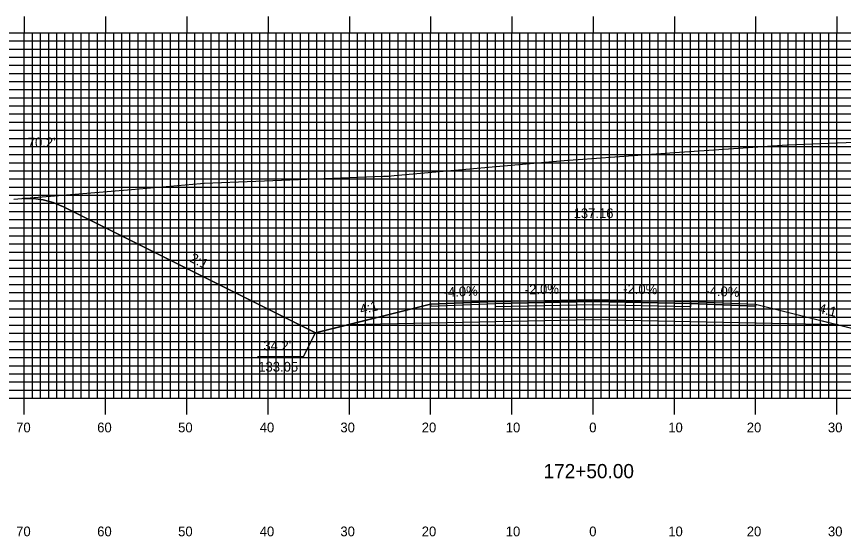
# Model space of a CAD drawing. Extents: x 1783041 to 1783384, y 442591 to 442811.
# Drawn here: x 1783135.5 to 1783237.3, y 442656.6 to 442720.7 of the extents above; entities that cross this region are included whole.
import ezdxf

# ---------------------------------------------------------------- set-up
doc = ezdxf.new("R2010")
doc.units = 0
for name, color, linetype in [('ANNOTATION', 7, 'Continuous'), ('D_Roadway_Centerline', 7, 'Continuous'), ('D_Roadway_Centerline_Text', 7, 'Continuous'), ('D_Roadway_Edge_Shoulder', 7, 'Continuous'), ('D_Roadway_Edge_TW', 7, 'Continuous'), ('D_Roadway_Pavement', 7, 'Continuous'), ('D_Roadway_SlopeLines', 7, 'Continuous'), ('D_Roadway_SubGrade', 7, 'Continuous'), ('D_Text_Standard', 7, 'Continuous'), ('H_V ANNOTATION', 7, 'Continuous'), ('MAJOR', 7, 'Continuous'), ('MINOR', 7, 'Continuous'), ('S_Roadway_Centerline', 7, 'Continuous')]:
    doc.layers.add(name, color=color, linetype=linetype)

msp = doc.modelspace()

# ---------------------------------------------------------------- linework, layer by layer
at = {"layer": 'ANNOTATION'}
msp.add_lwpolyline([(1783165.14, 442678.82), (1783170.83, 442678.82), (1783172.29, 442681.72)], dxfattribs=at)
at = {"layer": 'D_Roadway_Centerline'}
msp.add_lwpolyline([(1783136.28, 442698.26), (1783137.53, 442698.27), (1783138.78, 442698.11), (1783140.03, 442697.76), (1783141.28, 442697.22), (1783172.29, 442681.72), (1783176.29, 442682.72), (1783186.46, 442685.26), (1783194.46, 442685.58), (1783206.46, 442685.82), (1783218.46, 442685.58), (1783226.46, 442685.26), (1783236.63, 442682.72), (1783242.72, 442681.2), (1783297.77, 442708.72), (1783299.02, 442709.26), (1783300.27, 442709.64), (1783301.52, 442709.85), (1783302.77, 442709.89)], dxfattribs=at)
at = {"layer": 'D_Roadway_Edge_Shoulder'}
for points in [[(1783194.46, 442685.58), (1783186.46, 442685.26), (1783186.46, 442685.01), (1783194.46, 442685.33)], [(1783218.46, 442685.58), (1783226.46, 442685.26), (1783226.46, 442685.01), (1783218.46, 442685.33)]]:
    msp.add_lwpolyline(points, close=True, dxfattribs=at)
at = {"layer": 'D_Roadway_Edge_TW'}
msp.add_lwpolyline([(1783194.46, 442685.33), (1783194.46, 442685.58), (1783206.46, 442685.82), (1783218.46, 442685.58), (1783218.46, 442685.33), (1783206.46, 442685.57)], close=True, dxfattribs=at)
at = {"layer": 'D_Roadway_Pavement'}
msp.add_lwpolyline([(1783194.46, 442684.91), (1783194.46, 442685.33), (1783206.46, 442685.57), (1783218.46, 442685.33), (1783218.46, 442684.91), (1783206.46, 442685.15)], close=True, dxfattribs=at)
at = {"layer": 'D_Roadway_SlopeLines'}
for points in [[(1783172.29, 442681.72), (1783141.28, 442697.22), (1783140.03, 442697.76), (1783138.78, 442698.11), (1783137.53, 442698.27), (1783136.28, 442698.26)], [(1783186.46, 442685.26), (1783172.29, 442681.72)], [(1783226.46, 442685.26), (1783242.72, 442681.2)]]:
    msp.add_lwpolyline(points, dxfattribs=at)
at = {"layer": 'D_Roadway_SubGrade'}
msp.add_lwpolyline([(1783194.46, 442683.08), (1783176.29, 442682.72), (1783186.46, 442685.26), (1783186.46, 442685.01), (1783194.46, 442685.33), (1783206.46, 442685.57), (1783218.46, 442685.33), (1783226.46, 442685.01), (1783226.46, 442685.26), (1783236.63, 442682.72), (1783218.46, 442683.08), (1783206.46, 442683.32)], close=True, dxfattribs=at)
at = {"layer": 'MAJOR'}
for p, q in [((1783136.46, 442720.67), (1783136.46, 442718.67)), ((1783146.46, 442720.67), (1783146.46, 442718.67)), ((1783156.46, 442720.67), (1783156.46, 442718.67)), ((1783166.46, 442720.67), (1783166.46, 442718.67)), ((1783176.46, 442720.67), (1783176.46, 442718.67)), ((1783186.46, 442720.67), (1783186.46, 442718.67)), ((1783196.46, 442720.67), (1783196.46, 442718.67)), ((1783206.46, 442720.67), (1783206.46, 442718.67)), ((1783216.46, 442720.67), (1783216.46, 442718.67)), ((1783226.46, 442720.67), (1783226.46, 442718.67)), ((1783236.46, 442720.67), (1783236.46, 442718.67)), ((1783066.46, 442718.67), (1783346.46, 442718.67)), ((1783066.46, 442718.67), (1783346.46, 442718.67)), ((1783136.46, 442673.67), (1783136.46, 442718.67)), ((1783146.46, 442673.67), (1783146.46, 442718.67)), ((1783156.46, 442673.67), (1783156.46, 442718.67)), ((1783166.46, 442673.67), (1783166.46, 442718.67)), ((1783176.46, 442673.67), (1783176.46, 442718.67)), ((1783186.46, 442673.67), (1783186.46, 442718.67)), ((1783196.46, 442673.67), (1783196.46, 442718.67)), ((1783206.46, 442673.67), (1783206.46, 442718.67)), ((1783216.46, 442673.67), (1783216.46, 442718.67)), ((1783226.46, 442673.67), (1783226.46, 442718.67)), ((1783236.46, 442673.67), (1783236.46, 442718.67)), ((1783066.46, 442713.67), (1783346.46, 442713.67)), ((1783066.46, 442708.67), (1783346.46, 442708.67)), ((1783066.46, 442703.67), (1783346.46, 442703.67)), ((1783066.46, 442698.67), (1783346.46, 442698.67)), ((1783066.46, 442693.67), (1783346.46, 442693.67)), ((1783066.46, 442688.67), (1783346.46, 442688.67)), ((1783066.46, 442683.67), (1783346.46, 442683.67)), ((1783066.46, 442678.67), (1783346.46, 442678.67)), ((1783066.46, 442673.67), (1783346.46, 442673.67)), ((1783066.46, 442673.67), (1783346.46, 442673.67)), ((1783136.46, 442671.66), (1783136.46, 442673.67)), ((1783146.46, 442671.66), (1783146.46, 442673.67)), ((1783156.46, 442671.66), (1783156.46, 442673.67)), ((1783166.46, 442671.66), (1783166.46, 442673.67)), ((1783176.46, 442671.66), (1783176.46, 442673.67)), ((1783186.46, 442671.66), (1783186.46, 442673.67)), ((1783196.46, 442671.66), (1783196.46, 442673.67)), ((1783206.46, 442671.66), (1783206.46, 442673.67)), ((1783216.46, 442671.66), (1783216.46, 442673.67)), ((1783226.46, 442671.66), (1783226.46, 442673.67)), ((1783236.46, 442671.66), (1783236.46, 442673.67))]:
    msp.add_line(p, q, dxfattribs=at)
at = {"layer": 'MINOR'}
for p, q in [((1783137.46, 442673.67), (1783137.46, 442718.67)), ((1783138.46, 442673.67), (1783138.46, 442718.67)), ((1783139.46, 442673.67), (1783139.46, 442718.67)), ((1783140.46, 442673.67), (1783140.46, 442718.67)), ((1783141.46, 442673.67), (1783141.46, 442718.67)), ((1783142.46, 442673.67), (1783142.46, 442718.67)), ((1783143.46, 442673.67), (1783143.46, 442718.67)), ((1783144.46, 442673.67), (1783144.46, 442718.67)), ((1783145.46, 442673.67), (1783145.46, 442718.67)), ((1783147.46, 442673.67), (1783147.46, 442718.67)), ((1783148.46, 442673.67), (1783148.46, 442718.67)), ((1783149.46, 442673.67), (1783149.46, 442718.67)), ((1783150.46, 442673.67), (1783150.46, 442718.67)), ((1783151.46, 442673.67), (1783151.46, 442718.67)), ((1783152.46, 442673.67), (1783152.46, 442718.67)), ((1783153.46, 442673.67), (1783153.46, 442718.67)), ((1783154.46, 442673.67), (1783154.46, 442718.67)), ((1783155.46, 442673.67), (1783155.46, 442718.67)), ((1783157.46, 442673.67), (1783157.46, 442718.67)), ((1783158.46, 442673.67), (1783158.46, 442718.67)), ((1783159.46, 442673.67), (1783159.46, 442718.67)), ((1783160.46, 442673.67), (1783160.46, 442718.67)), ((1783161.46, 442673.67), (1783161.46, 442718.67)), ((1783162.46, 442673.67), (1783162.46, 442718.67)), ((1783163.46, 442673.67), (1783163.46, 442718.67)), ((1783164.46, 442673.67), (1783164.46, 442718.67)), ((1783165.46, 442673.67), (1783165.46, 442718.67)), ((1783167.46, 442673.67), (1783167.46, 442718.67)), ((1783168.46, 442673.67), (1783168.46, 442718.67)), ((1783169.46, 442673.67), (1783169.46, 442718.67)), ((1783170.46, 442673.67), (1783170.46, 442718.67)), ((1783171.46, 442673.67), (1783171.46, 442718.67)), ((1783172.46, 442673.67), (1783172.46, 442718.67)), ((1783173.46, 442673.67), (1783173.46, 442718.67)), ((1783174.46, 442673.67), (1783174.46, 442718.67)), ((1783175.46, 442673.67), (1783175.46, 442718.67)), ((1783177.46, 442673.67), (1783177.46, 442718.67)), ((1783178.46, 442673.67), (1783178.46, 442718.67)), ((1783179.46, 442673.67), (1783179.46, 442718.67)), ((1783180.46, 442673.67), (1783180.46, 442718.67)), ((1783181.46, 442673.67), (1783181.46, 442718.67)), ((1783182.46, 442673.67), (1783182.46, 442718.67)), ((1783183.46, 442673.67), (1783183.46, 442718.67)), ((1783184.46, 442673.67), (1783184.46, 442718.67)), ((1783185.46, 442673.67), (1783185.46, 442718.67)), ((1783187.46, 442673.67), (1783187.46, 442718.67)), ((1783188.46, 442673.67), (1783188.46, 442718.67)), ((1783189.46, 442673.67), (1783189.46, 442718.67)), ((1783190.46, 442673.67), (1783190.46, 442718.67)), ((1783191.46, 442673.67), (1783191.46, 442718.67)), ((1783192.46, 442673.67), (1783192.46, 442718.67)), ((1783193.46, 442673.67), (1783193.46, 442718.67)), ((1783194.46, 442673.67), (1783194.46, 442718.67)), ((1783195.46, 442673.67), (1783195.46, 442718.67)), ((1783197.46, 442673.67), (1783197.46, 442718.67)), ((1783198.46, 442673.67), (1783198.46, 442718.67)), ((1783199.46, 442673.67), (1783199.46, 442718.67)), ((1783200.46, 442673.67), (1783200.46, 442718.67)), ((1783201.46, 442673.67), (1783201.46, 442718.67)), ((1783202.46, 442673.67), (1783202.46, 442718.67)), ((1783203.46, 442673.67), (1783203.46, 442718.67)), ((1783204.46, 442673.67), (1783204.46, 442718.67)), ((1783205.46, 442673.67), (1783205.46, 442718.67)), ((1783207.46, 442673.67), (1783207.46, 442718.67)), ((1783208.46, 442673.67), (1783208.46, 442718.67)), ((1783209.46, 442673.67), (1783209.46, 442718.67)), ((1783210.46, 442673.67), (1783210.46, 442718.67)), ((1783211.46, 442673.67), (1783211.46, 442718.67)), ((1783212.46, 442673.67), (1783212.46, 442718.67)), ((1783213.46, 442673.67), (1783213.46, 442718.67)), ((1783214.46, 442673.67), (1783214.46, 442718.67)), ((1783215.46, 442673.67), (1783215.46, 442718.67)), ((1783217.46, 442673.67), (1783217.46, 442718.67)), ((1783218.46, 442673.67), (1783218.46, 442718.67)), ((1783219.46, 442673.67), (1783219.46, 442718.67)), ((1783220.46, 442673.67), (1783220.46, 442718.67)), ((1783221.46, 442673.67), (1783221.46, 442718.67)), ((1783222.46, 442673.67), (1783222.46, 442718.67)), ((1783223.46, 442673.67), (1783223.46, 442718.67)), ((1783224.46, 442673.67), (1783224.46, 442718.67)), ((1783225.46, 442673.67), (1783225.46, 442718.67)), ((1783227.46, 442673.67), (1783227.46, 442718.67)), ((1783228.46, 442673.67), (1783228.46, 442718.67)), ((1783229.46, 442673.67), (1783229.46, 442718.67)), ((1783230.46, 442673.67), (1783230.46, 442718.67)), ((1783231.46, 442673.67), (1783231.46, 442718.67)), ((1783232.46, 442673.67), (1783232.46, 442718.67)), ((1783233.46, 442673.67), (1783233.46, 442718.67)), ((1783234.46, 442673.67), (1783234.46, 442718.67)), ((1783235.46, 442673.67), (1783235.46, 442718.67)), ((1783066.46, 442717.67), (1783346.46, 442717.67)), ((1783066.46, 442716.67), (1783346.46, 442716.67)), ((1783066.46, 442715.67), (1783346.46, 442715.67)), ((1783066.46, 442714.67), (1783346.46, 442714.67)), ((1783066.46, 442712.67), (1783346.46, 442712.67)), ((1783066.46, 442711.67), (1783346.46, 442711.67)), ((1783066.46, 442710.67), (1783346.46, 442710.67)), ((1783066.46, 442709.67), (1783346.46, 442709.67)), ((1783066.46, 442707.67), (1783346.46, 442707.67)), ((1783066.46, 442706.67), (1783346.46, 442706.67)), ((1783066.46, 442705.67), (1783346.46, 442705.67)), ((1783066.46, 442704.67), (1783346.46, 442704.67)), ((1783066.46, 442702.67), (1783346.46, 442702.67)), ((1783066.46, 442701.67), (1783346.46, 442701.67)), ((1783066.46, 442700.67), (1783346.46, 442700.67)), ((1783066.46, 442699.67), (1783346.46, 442699.67)), ((1783066.46, 442697.67), (1783346.46, 442697.67)), ((1783066.46, 442696.67), (1783346.46, 442696.67)), ((1783066.46, 442695.67), (1783346.46, 442695.67)), ((1783066.46, 442694.67), (1783346.46, 442694.67)), ((1783066.46, 442692.67), (1783346.46, 442692.67)), ((1783066.46, 442691.67), (1783346.46, 442691.67)), ((1783066.46, 442690.67), (1783346.46, 442690.67)), ((1783066.46, 442689.67), (1783346.46, 442689.67)), ((1783066.46, 442687.67), (1783346.46, 442687.67)), ((1783066.46, 442686.67), (1783346.46, 442686.67)), ((1783066.46, 442685.67), (1783346.46, 442685.67)), ((1783066.46, 442684.67), (1783346.46, 442684.67)), ((1783066.46, 442682.67), (1783346.46, 442682.67)), ((1783066.46, 442681.67), (1783346.46, 442681.67)), ((1783066.46, 442680.67), (1783346.46, 442680.67)), ((1783066.46, 442679.67), (1783346.46, 442679.67)), ((1783066.46, 442677.67), (1783346.46, 442677.67)), ((1783066.46, 442676.67), (1783346.46, 442676.67)), ((1783066.46, 442675.67), (1783346.46, 442675.67)), ((1783066.46, 442674.67), (1783346.46, 442674.67))]:
    msp.add_line(p, q, dxfattribs=at)
at = {"layer": 'S_Roadway_Centerline'}
msp.add_lwpolyline([(1783135.18, 442698.17), (1783149.65, 442699.39), (1783158.14, 442700.11), (1783158.59, 442700.16), (1783164.96, 442700.39), (1783180.67, 442701), (1783181.26, 442701.02), (1783181.98, 442701.08), (1783203.36, 442702.98), (1783204.01, 442703.02), (1783204.63, 442703.06), (1783215.92, 442703.87), (1783230.35, 442704.87), (1783239.64, 442705.26)], dxfattribs=at)

# ---------------------------------------------------------------- texts
at = {"layer": 'ANNOTATION'}
for s, rotation, p in [('2:1', 333.4349, (1783156.72, 442690.54)), ('-2.0%', 1.1458, (1783198.07, 442686.45)), ('-2.0%', 358.8542, (1783210.15, 442686.55)), ('-4.0%', 2.2906, (1783188.09, 442686.13)), ('-4.0%', 357.7094, (1783220.25, 442686.31)), ('4:1', 14.0362, (1783177.91, 442683.98)), ('4:1', 345.9638, (1783234.1, 442684.21))]:
    msp.add_text(s, height=1.2, rotation=rotation, dxfattribs=at).set_placement(p)
for s, p in [("34.2'", (1783165.88, 442679.55)), ('133.05', (1783165.25, 442676.95))]:
    msp.add_text(s, height=1.2, dxfattribs=at).set_placement(p)
at = {"layer": 'D_Roadway_Centerline'}
for s, p in [('C', (1783206.45, 442685.82)), ('L', (1783206.46, 442685.81))]:
    msp.add_text(s, height=0.0146, dxfattribs=at).set_placement(p)
at = {"layer": 'D_Roadway_Centerline_Text'}
msp.add_text('137.16', height=1.2, dxfattribs=at).set_placement((1783204.06, 442695.85))
at = {"layer": 'D_Text_Standard'}
msp.add_text("70.2'", height=1.2, dxfattribs=at).set_placement((1783136.88, 442704.57))
at = {"layer": 'H_V ANNOTATION'}
for s, height, p in [('70', 1.2, (1783135.46, 442669.47)), ('60', 1.2, (1783145.43, 442669.47)), ('50', 1.2, (1783155.39, 442669.47)), ('40', 1.2, (1783165.43, 442669.47)), ('30', 1.2, (1783175.36, 442669.47)), ('20', 1.2, (1783185.37, 442669.47)), ('10', 1.2, (1783195.71, 442669.47)), ('0', 1.2, (1783205.98, 442669.47)), ('10', 1.2, (1783215.71, 442669.47)), ('20', 1.2, (1783225.37, 442669.47)), ('30', 1.2, (1783235.36, 442669.47)), ('172+50.00', 1.75, (1783200.36, 442663.82)), ('70', 1.2, (1783135.46, 442656.67)), ('60', 1.2, (1783145.43, 442656.67)), ('50', 1.2, (1783155.39, 442656.67)), ('40', 1.2, (1783165.43, 442656.67)), ('30', 1.2, (1783175.36, 442656.67)), ('20', 1.2, (1783185.37, 442656.67)), ('10', 1.2, (1783195.71, 442656.67)), ('0', 1.2, (1783205.98, 442656.67)), ('10', 1.2, (1783215.71, 442656.67)), ('20', 1.2, (1783225.37, 442656.67)), ('30', 1.2, (1783235.36, 442656.67))]:
    msp.add_text(s, height=height, dxfattribs=at).set_placement(p)

doc.saveas('drawing.dxf')
